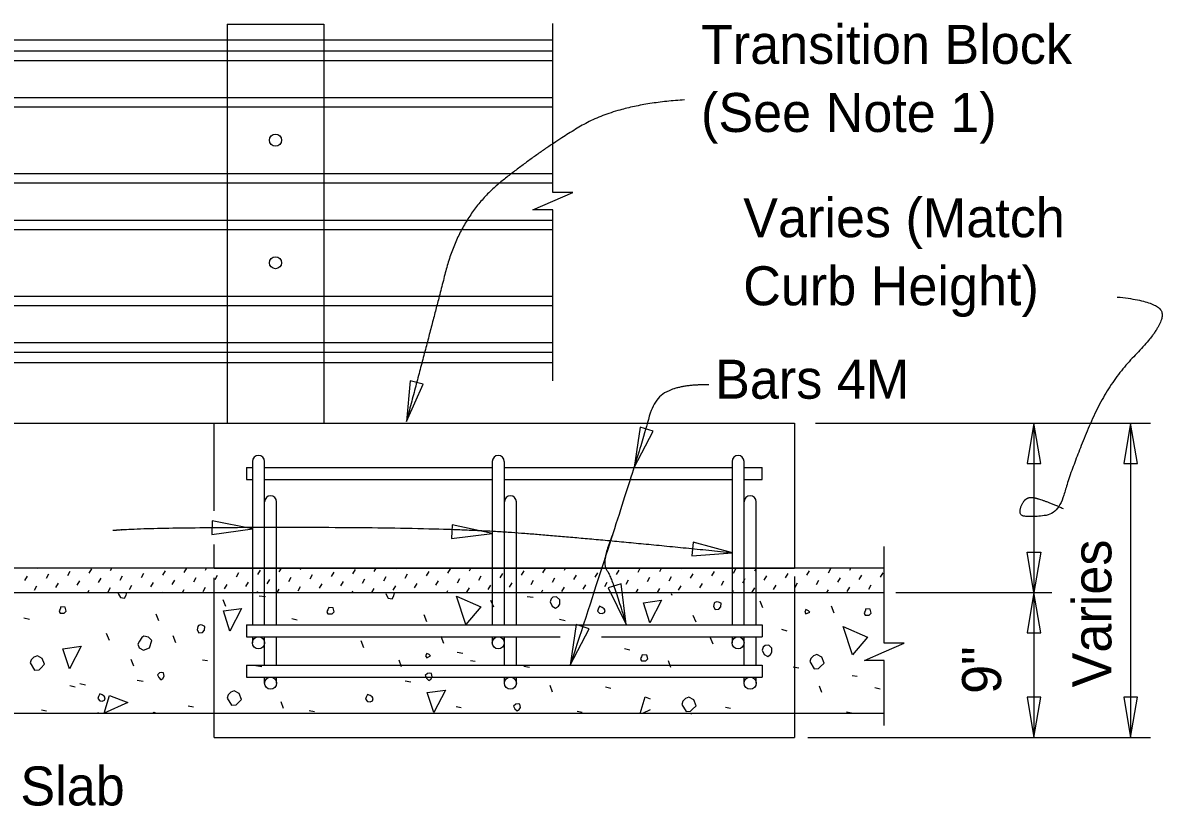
# Model space of a CAD drawing. Extents: x 21526.6 to 21598.7, y 56118.9 to 56155.9.
# Drawn here: x 21561.42 to 21567.31, y 56133.17 to 56137.28 of the extents above; entities that cross this region are included whole.
import ezdxf

# ---------------------------------------------------------------- set-up
doc = ezdxf.new("R2010")
doc.units = 0
for name, color, linetype in [('AdhocPoint_dp', 7, 'Continuous'), ('Border', 7, 'Continuous'), ('Patterning', 7, 'Continuous'), ('PlotBorder_dp', 7, 'Continuous'), ('SheetBorder_dp', 7, 'Continuous'), ('SheetLines_dp', 7, 'Continuous'), ('SubStrConc', 7, 'Continuous'), ('SubStrConc_h', 7, 'Continuous')]:
    doc.layers.add(name, color=color, linetype=linetype)

msp = doc.modelspace()

# ---------------------------------------------------------------- linework, layer by layer
at = {"layer": 'AdhocPoint_dp'}
for p, q in [((21554.3018, 56135.21), (21562.4118, 56135.21)), ((21565.8764, 56134.4601), (21554.3018, 56134.4601)), ((21554.3018, 56134.3351), (21565.8764, 56134.3351)), ((21565.8764, 56133.71), (21559.5217, 56133.71))]:
    msp.add_line(p, q, dxfattribs=at)
at = {"layer": 'Patterning'}
for p, q in [((21562.4788, 56137.2725), (21562.4788, 56135.21)), ((21562.4788, 56137.2725), (21562.9788, 56137.2725)), ((21562.9788, 56137.2725), (21562.9788, 56135.21)), ((21561.4336, 56134.3964), (21561.4465, 56134.4187)), ((21561.4954, 56134.4582), (21561.4965, 56134.4601)), ((21561.5442, 56134.4093), (21561.5572, 56134.4317)), ((21561.6548, 56134.4223), (21561.6678, 56134.4447)), ((21561.7655, 56134.4352), (21561.7784, 56134.4576)), ((21561.8761, 56134.4482), (21561.883, 56134.4601)), ((21561.9249, 56134.3994), (21561.9379, 56134.4218)), ((21562.0356, 56134.4123), (21562.0485, 56134.4347)), ((21562.1462, 56134.4253), (21562.1592, 56134.4477)), ((21562.2568, 56134.4383), (21562.2695, 56134.4601)), ((21562.3675, 56134.4512), (21562.3726, 56134.4601)), ((21562.4163, 56134.4024), (21562.4293, 56134.4248)), ((21562.5269, 56134.4154), (21562.5399, 56134.4377)), ((21562.6376, 56134.4283), (21562.6505, 56134.4507)), ((21562.7482, 56134.4413), (21562.7591, 56134.4601)), ((21562.797, 56134.3925), (21562.81, 56134.4148)), ((21562.8588, 56134.4542), (21562.8622, 56134.4601)), ((21562.9077, 56134.4054), (21562.9206, 56134.4278)), ((21563.0183, 56134.4184), (21563.0312, 56134.4408)), ((21563.1289, 56134.4313), (21563.1419, 56134.4537)), ((21563.2396, 56134.4443), (21563.2487, 56134.4601)), ((21563.2884, 56134.3955), (21563.3013, 56134.4179)), ((21563.3502, 56134.4573), (21563.3518, 56134.4601)), ((21563.399, 56134.4084), (21563.412, 56134.4308)), ((21563.5097, 56134.4214), (21563.5226, 56134.4438)), ((21563.6203, 56134.4344), (21563.6332, 56134.4568)), ((21563.7309, 56134.4473), (21563.7383, 56134.4601)), ((21563.7798, 56134.3985), (21563.7927, 56134.4209)), ((21563.8904, 56134.4115), (21563.9033, 56134.4338)), ((21564.001, 56134.4244), (21564.014, 56134.4468)), ((21564.1116, 56134.4374), (21564.1246, 56134.4598)), ((21564.2223, 56134.4503), (21564.2279, 56134.4601)), ((21564.2711, 56134.4015), (21564.2841, 56134.4239)), ((21564.3817, 56134.4145), (21564.3947, 56134.4369)), ((21564.4924, 56134.4274), (21564.5053, 56134.4498)), ((21564.603, 56134.4404), (21564.6144, 56134.4601)), ((21564.6518, 56134.3916), (21564.6648, 56134.414)), ((21564.7151, 56134.4443), (21564.7243, 56134.4601)), ((21564.764, 56134.3955), (21564.7769, 56134.4179)), ((21564.8258, 56134.4573), (21564.8274, 56134.4601)), ((21564.8746, 56134.4084), (21564.8876, 56134.4308)), ((21564.9852, 56134.4214), (21564.9982, 56134.4438)), ((21565.0959, 56134.4344), (21565.1088, 56134.4568)), ((21565.2065, 56134.4473), (21565.2139, 56134.4601)), ((21565.2553, 56134.3985), (21565.2683, 56134.4209)), ((21565.366, 56134.4115), (21565.3789, 56134.4338)), ((21565.4766, 56134.4244), (21565.4896, 56134.4468)), ((21565.5872, 56134.4374), (21565.6002, 56134.4598)), ((21565.6979, 56134.4503), (21565.7035, 56134.4601)), ((21565.7467, 56134.4015), (21565.7597, 56134.4239)), ((21565.8573, 56134.4145), (21565.8703, 56134.4369)), ((21561.4824, 56134.3475), (21561.4954, 56134.3699)), ((21561.593, 56134.3605), (21561.606, 56134.3829)), ((21561.7037, 56134.3734), (21561.7166, 56134.3958)), ((21561.8143, 56134.3864), (21561.8273, 56134.4088)), ((21561.8631, 56134.3376), (21561.8761, 56134.36)), ((21561.9738, 56134.3505), (21561.9867, 56134.3729)), ((21562.0844, 56134.3635), (21562.0974, 56134.3859)), ((21562.195, 56134.3765), (21562.208, 56134.3989)), ((21562.3057, 56134.3894), (21562.3186, 56134.4118)), ((21562.3545, 56134.3406), (21562.3675, 56134.363)), ((21562.4651, 56134.3536), (21562.4781, 56134.376)), ((21562.5758, 56134.3665), (21562.5887, 56134.3889)), ((21562.6864, 56134.3795), (21562.6994, 56134.4019)), ((21562.8459, 56134.3436), (21562.8588, 56134.366)), ((21562.9565, 56134.3566), (21562.9695, 56134.379)), ((21563.0671, 56134.3695), (21563.0801, 56134.3919)), ((21563.1778, 56134.3825), (21563.1907, 56134.4049)), ((21563.2274, 56134.3351), (21563.2396, 56134.3561)), ((21563.3372, 56134.3466), (21563.3502, 56134.369)), ((21563.4479, 56134.3596), (21563.4608, 56134.382)), ((21563.5585, 56134.3726), (21563.5714, 56134.395)), ((21563.6691, 56134.3855), (21563.6821, 56134.4079)), ((21563.718, 56134.3367), (21563.7309, 56134.3591)), ((21563.8286, 56134.3497), (21563.8415, 56134.372)), ((21563.9392, 56134.3626), (21563.9522, 56134.385)), ((21564.0499, 56134.3756), (21564.0628, 56134.398)), ((21564.1605, 56134.3885), (21564.1734, 56134.4109)), ((21564.2093, 56134.3397), (21564.2223, 56134.3621)), ((21564.32, 56134.3527), (21564.3329, 56134.3751)), ((21564.4306, 56134.3656), (21564.4435, 56134.388)), ((21564.5412, 56134.3786), (21564.5542, 56134.401)), ((21564.703, 56134.3351), (21564.7151, 56134.3561)), ((21564.8128, 56134.3466), (21564.8258, 56134.369)), ((21564.9234, 56134.3596), (21564.9364, 56134.382)), ((21565.0341, 56134.3726), (21565.047, 56134.395)), ((21565.1447, 56134.3855), (21565.1577, 56134.4079)), ((21565.1935, 56134.3367), (21565.2065, 56134.3591)), ((21565.3042, 56134.3497), (21565.3171, 56134.372)), ((21565.4148, 56134.3626), (21565.4278, 56134.385)), ((21565.5254, 56134.3756), (21565.5384, 56134.398)), ((21565.6361, 56134.3885), (21565.649, 56134.4109)), ((21565.6849, 56134.3397), (21565.6979, 56134.3621)), ((21565.7955, 56134.3527), (21565.8085, 56134.3751)), ((21561.7585, 56134.3351), (21561.7655, 56134.347)), ((21562.145, 56134.3351), (21562.1462, 56134.3371)), ((21562.2482, 56134.3351), (21562.2568, 56134.35)), ((21562.4721, 56134.2625), (21562.458, 56134.2979)), ((21562.6346, 56134.3351), (21562.6376, 56134.3401)), ((21562.6448, 56134.3185), (21562.6766, 56134.315)), ((21562.7378, 56134.3351), (21562.7482, 56134.353)), ((21563.1243, 56134.3351), (21563.1289, 56134.3431)), ((21563.6139, 56134.3351), (21563.6203, 56134.3461)), ((21564.0004, 56134.3351), (21564.001, 56134.3362)), ((21564.0294, 56134.315), (21564.0613, 56134.3114)), ((21564.1035, 56134.3351), (21564.1116, 56134.3491)), ((21564.49, 56134.3351), (21564.4924, 56134.3392)), ((21564.5931, 56134.3351), (21564.603, 56134.3522)), ((21565.0895, 56134.3351), (21565.0959, 56134.3461)), ((21565.476, 56134.3351), (21565.4766, 56134.3362)), ((21565.5791, 56134.3351), (21565.5872, 56134.3491)), ((21563.8568, 56134.259), (21563.8427, 56134.2944)), ((21565.2489, 56134.2557), (21565.2347, 56134.291)), ((21565.6176, 56134.2282), (21565.6035, 56134.2636)), ((21561.428, 56134.2036), (21561.4563, 56134.1965)), ((21562.1263, 56134.1877), (21562.1121, 56134.223)), ((21562.8127, 56134.2001), (21562.841, 56134.193)), ((21563.511, 56134.1841), (21563.4968, 56134.2195)), ((21564.1974, 56134.1965), (21564.2257, 56134.1894)), ((21564.903, 56134.1808), (21564.8889, 56134.2161)), ((21561.87, 56134.0869), (21561.8558, 56134.1223)), ((21565.3441, 56134.1447), (21565.3724, 56134.1376)), ((21562.214, 56134.0752), (21562.1999, 56134.1105)), ((21563.1862, 56134.0491), (21563.172, 56134.0845)), ((21563.5987, 56134.0716), (21563.5846, 56134.107)), ((21564.9908, 56134.0683), (21564.9767, 56134.1036)), ((21563.6672, 56134.0268), (21563.6973, 56134.0215)), ((21564.5329, 56134.0454), (21564.5612, 56134.0384)), ((21561.9955, 56133.9543), (21561.9831, 56133.9879)), ((21562.3519, 56133.9868), (21562.3767, 56133.9832)), ((21562.6277, 56133.9585), (21562.6578, 56133.9532)), ((21563.3802, 56133.9508), (21563.3678, 56133.9844)), ((21563.7366, 56133.9832), (21563.7614, 56133.9797)), ((21564.0124, 56133.955), (21564.0424, 56133.9497)), ((21564.7722, 56133.9474), (21564.7598, 56133.981)), ((21565.4045, 56133.9516), (21565.4345, 56133.9463)), ((21565.7105, 56133.9057), (21565.7353, 56133.9022)), ((21561.6655, 56133.8542), (21561.6938, 56133.8471)), ((21561.7179, 56133.8642), (21561.7462, 56133.8571)), ((21562.0143, 56133.8825), (21562.0443, 56133.8772)), ((21563.399, 56133.8789), (21563.429, 56133.8736)), ((21564.1609, 56133.8206), (21564.1485, 56133.8542)), ((21564.4349, 56133.8471), (21564.4632, 56133.8401)), ((21565.5529, 56133.8173), (21565.5406, 56133.8508)), ((21565.8269, 56133.8438), (21565.8552, 56133.8367)), ((21562.7705, 56133.7357), (21562.7581, 56133.7693)), ((21561.5188, 56133.7287), (21561.5453, 56133.7234)), ((21561.8135, 56133.71), (21561.8116, 56133.7152)), ((21562.2777, 56133.7499), (21562.3042, 56133.7446)), ((21562.9035, 56133.7251), (21562.93, 56133.7198)), ((21563.1969, 56133.71), (21563.1963, 56133.7116)), ((21563.6624, 56133.7464), (21563.6889, 56133.7411)), ((21564.2882, 56133.7216), (21564.3147, 56133.7163)), ((21565.0544, 56133.743), (21565.0809, 56133.7377)), ((21565.6802, 56133.7183), (21565.7067, 56133.713))]:
    msp.add_line(p, q, dxfattribs=at)
for points in [[(21561.915, 56134.3351), (21561.9142, 56134.3326), (21561.9177, 56134.3256)], [(21561.9177, 56134.3256), (21561.9265, 56134.3097), (21561.9477, 56134.3061), (21561.9566, 56134.322), (21561.9598, 56134.3351)], [(21563.3008, 56134.3351), (21563.2988, 56134.3291), (21563.3024, 56134.322)], [(21563.3024, 56134.322), (21563.3112, 56134.3061), (21563.3324, 56134.3026), (21563.3413, 56134.3185), (21563.3448, 56134.3326), (21563.3424, 56134.3351)], [(21563.7121, 56134.1696), (21563.6644, 56134.3163), (21563.7899, 56134.2615), (21563.7121, 56134.1696)], [(21564.1486, 56134.2859), (21564.1592, 56134.2647), (21564.1769, 56134.2541), (21564.191, 56134.2647), (21564.1981, 56134.2753), (21564.1981, 56134.2965), (21564.1822, 56134.3124), (21564.1627, 56134.3106), (21564.1539, 56134.3018), (21564.1486, 56134.2859)], [(21564.7764, 56134.3351), (21564.7744, 56134.3291), (21564.7779, 56134.322)], [(21561.6154, 56134.2283), (21561.6366, 56134.2283), (21561.6472, 56134.2389), (21561.6419, 56134.2584), (21561.6189, 56134.2602), (21561.6154, 56134.2495), (21561.6101, 56134.2407), (21561.6154, 56134.2283), (21561.6119, 56134.2319)], [(21562.4929, 56134.1357), (21562.4593, 56134.24), (21562.553, 56134.2524), (21562.4929, 56134.1357)], [(21563.0001, 56134.2248), (21563.0213, 56134.2248), (21563.0319, 56134.2354), (21563.0266, 56134.2549), (21563.0036, 56134.2566), (21563.0001, 56134.246), (21562.9948, 56134.2372), (21563.0001, 56134.2248), (21562.9965, 56134.2283)], [(21564.4044, 56134.2281), (21564.4168, 56134.2263), (21564.4292, 56134.2316), (21564.4327, 56134.2423), (21564.4274, 56134.2511), (21564.4168, 56134.2582), (21564.4044, 56134.2635), (21564.3973, 56134.2493), (21564.3938, 56134.2387), (21564.4044, 56134.2281)], [(21564.6643, 56134.1779), (21564.6307, 56134.2822), (21564.7244, 56134.2945), (21564.6643, 56134.1779)], [(21564.9933, 56134.2627), (21565.0022, 56134.2468), (21565.0216, 56134.2485), (21565.0304, 56134.2609), (21565.0322, 56134.2803), (21565.0198, 56134.2856), (21565.011, 56134.2874), (21565.0004, 56134.2839), (21564.9968, 56134.2803), (21564.9933, 56134.2627)], [(21565.4713, 56134.2251), (21565.4908, 56134.2339), (21565.4837, 56134.241), (21565.4713, 56134.2463), (21565.466, 56134.2339), (21565.4713, 56134.2251)], [(21565.7768, 56134.2179), (21565.798, 56134.2179), (21565.8086, 56134.2285), (21565.8033, 56134.248), (21565.7804, 56134.2497), (21565.7768, 56134.2391), (21565.7715, 56134.2303), (21565.7768, 56134.2179), (21565.7733, 56134.2215)], [(21562.3237, 56134.1423), (21562.3325, 56134.1264), (21562.3519, 56134.1282), (21562.3608, 56134.1406), (21562.3625, 56134.16), (21562.3502, 56134.1653), (21562.3413, 56134.1671), (21562.3307, 56134.1636), (21562.3272, 56134.16), (21562.3237, 56134.1423)], [(21565.7117, 56134.0122), (21565.664, 56134.1589), (21565.7895, 56134.1041), (21565.7117, 56134.0122)], [(21562.0238, 56134.0498), (21562.0467, 56134.0374), (21562.0768, 56134.0498), (21562.0892, 56134.0869), (21562.0715, 56134.1046), (21562.0485, 56134.1099), (21562.0379, 56134.1028), (21562.0255, 56134.0834), (21562.0167, 56134.0675), (21562.0238, 56134.0498)], [(21565.2454, 56134.0365), (21565.256, 56134.0152), (21565.2736, 56134.0046), (21565.2878, 56134.0152), (21565.2948, 56134.0259), (21565.2948, 56134.0471), (21565.2789, 56134.063), (21565.2595, 56134.0612), (21565.2507, 56134.0524), (21565.2454, 56134.0365)], [(21561.4605, 56133.9709), (21561.4834, 56133.9337), (21561.5064, 56133.9355), (21561.5153, 56133.9444), (21561.5347, 56133.9638), (21561.5223, 56133.9938), (21561.4976, 56134.008), (21561.4799, 56134.0009), (21561.4658, 56133.9868), (21561.4605, 56133.9709)], [(21561.6631, 56133.9402), (21561.6295, 56134.0445), (21561.7232, 56134.0569), (21561.6631, 56133.9402)], [(21563.5103, 56133.998), (21563.5298, 56134.0068), (21563.5227, 56134.0139), (21563.5103, 56134.0192), (21563.505, 56134.0068), (21563.5103, 56133.998)], [(21564.6215, 56133.9816), (21564.6427, 56133.9816), (21564.6533, 56133.9922), (21564.648, 56134.0116), (21564.625, 56134.0134), (21564.6215, 56134.0028), (21564.6162, 56133.994), (21564.6215, 56133.9816), (21564.618, 56133.9851)], [(21565.4907, 56133.9776), (21565.5137, 56133.9404), (21565.5366, 56133.9422), (21565.5455, 56133.9511), (21565.5649, 56133.9705), (21565.5526, 56134.0005), (21565.5278, 56134.0147), (21565.5101, 56134.0076), (21565.496, 56133.9935), (21565.4907, 56133.9776)], [(21562.1257, 56133.8949), (21562.1363, 56133.8842), (21562.1469, 56133.8913), (21562.1539, 56133.9019), (21562.1504, 56133.9196), (21562.1416, 56133.9214), (21562.1292, 56133.9196), (21562.1186, 56133.909), (21562.1257, 56133.8949)], [(21563.5103, 56133.8913), (21563.5209, 56133.8807), (21563.5316, 56133.8878), (21563.5386, 56133.8984), (21563.5351, 56133.9161), (21563.5262, 56133.9178), (21563.5139, 56133.9161), (21563.5033, 56133.9055), (21563.5103, 56133.8913)], [(21562.4785, 56133.7897), (21562.5015, 56133.7526), (21562.5245, 56133.7544), (21562.5333, 56133.7632), (21562.5528, 56133.7827), (21562.5404, 56133.8127), (21562.5156, 56133.8269), (21562.498, 56133.8198), (21562.4838, 56133.8056), (21562.4785, 56133.7897)], [(21563.547, 56133.7141), (21563.5134, 56133.8184), (21563.6071, 56133.8308), (21563.547, 56133.7141)], [(21561.8205, 56133.7758), (21561.8328, 56133.774), (21561.8452, 56133.7793), (21561.8487, 56133.7899), (21561.8434, 56133.7988), (21561.8328, 56133.8058), (21561.8205, 56133.8111), (21561.8134, 56133.797), (21561.8099, 56133.7864), (21561.8205, 56133.7758)], [(21561.8428, 56133.711), (21561.8711, 56133.8029), (21561.9648, 56133.7658), (21561.8428, 56133.711)], [(21563.2051, 56133.7723), (21563.2175, 56133.7705), (21563.2299, 56133.7758), (21563.2334, 56133.7864), (21563.2281, 56133.7952), (21563.2175, 56133.8023), (21563.2051, 56133.8076), (21563.1981, 56133.7935), (21563.1945, 56133.7829), (21563.2051, 56133.7723)], [(21564.6141, 56133.71), (21564.6405, 56133.7959), (21564.6652, 56133.7861)], [(21564.8288, 56133.7569), (21564.8518, 56133.7198), (21564.8748, 56133.7216), (21564.8836, 56133.7304), (21564.9031, 56133.7499), (21564.8907, 56133.7799), (21564.8659, 56133.794), (21564.8483, 56133.787), (21564.8341, 56133.7728), (21564.8288, 56133.7569)], [(21562.1099, 56133.71), (21562.1009, 56133.7145), (21562.0934, 56133.71)], [(21563.4875, 56133.71), (21563.4856, 56133.711), (21563.484, 56133.71)], [(21563.9669, 56133.7339), (21563.9775, 56133.7233), (21563.9881, 56133.7304), (21563.9951, 56133.741), (21563.9916, 56133.7586), (21563.9828, 56133.7604), (21563.9704, 56133.7586), (21563.9598, 56133.748), (21563.9669, 56133.7339)], [(21564.6652, 56133.7277), (21564.6258, 56133.71)], [(21564.8796, 56133.7067), (21564.8777, 56133.7077), (21564.876, 56133.7067)]]:
    msp.add_lwpolyline(points, dxfattribs=at)
at = {"layer": 'PlotBorder_dp'}
for p, q in [((21565.5209, 56135.21), (21567.2532, 56135.21)), ((21566.6495, 56135.21), (21566.6495, 56133.585)), ((21567.1495, 56135.21), (21567.1495, 56133.585)), ((21565.9364, 56134.335), (21566.742, 56134.335)), ((21565.4809, 56133.585), (21567.2532, 56133.585))]:
    msp.add_line(p, q, dxfattribs=at)
for points in [[(21564.1633, 56135.429), (21564.1633, 56136.3122), (21564.0599, 56136.3122), (21564.1633, 56136.3572), (21564.2666, 56136.4022), (21564.1633, 56136.4022), (21564.1633, 56137.2752)], [(21565.8764, 56133.6472), (21565.8764, 56133.9832), (21565.7731, 56133.9832), (21565.8764, 56134.0282), (21565.9797, 56134.0732), (21565.8764, 56134.0732), (21565.8764, 56134.5731)]]:
    msp.add_lwpolyline(points, dxfattribs=at)
for points in [[(21563.4053, 56135.2188), (21563.4928, 56135.4111), (21563.4245, 56135.4291)], [(21564.5839, 56134.9808), (21564.6819, 56135.1679), (21564.6148, 56135.1898)], [(21566.6495, 56135.21), (21566.6142, 56135.0017), (21566.6848, 56135.0017)], [(21567.1495, 56135.21), (21567.1142, 56135.0017), (21567.1848, 56135.0017)], [(21562.6093, 56134.6644), (21562.4019, 56134.7045), (21562.4003, 56134.634)], [(21563.8483, 56134.6403), (21563.6418, 56134.6846), (21563.6388, 56134.6141)], [(21565.0916, 56134.5393), (21564.8879, 56134.5955), (21564.8808, 56134.5253)], [(21566.6495, 56134.335), (21566.6142, 56134.5432), (21566.6848, 56134.5432)], [(21564.5411, 56134.1696), (21564.5162, 56134.3794), (21564.4485, 56134.3595)], [(21566.6495, 56134.335), (21566.6142, 56134.1267), (21566.6848, 56134.1267)], [(21564.2526, 56133.9599), (21564.3506, 56134.147), (21564.2835, 56134.1689)], [(21566.6495, 56133.585), (21566.6848, 56133.7933), (21566.6142, 56133.7933)], [(21567.1495, 56133.585), (21567.1848, 56133.7933), (21567.1142, 56133.7933)]]:
    msp.add_lwpolyline(points, close=True, dxfattribs=at)
for points in [[(21564.8436, 56136.8807), (21564.5025, 56136.8595), (21564.1187, 56136.6348), (21563.685, 56136.2922), (21563.5309, 56135.6927), (21563.4053, 56135.2188)], [(21567.0807, 56135.8621), (21567.3115, 56135.8395), (21567.3147, 56135.7056), (21567.0236, 56135.4087), (21566.8353, 56134.952), (21566.7782, 56134.7407), (21566.6298, 56134.7236), (21566.5671, 56134.735), (21566.6013, 56134.8264), (21566.6698, 56134.8264), (21566.8011, 56134.7693)], [(21564.9691, 56135.4078), (21564.8456, 56135.4112), (21564.6854, 56135.3477), (21564.6319, 56135.124), (21564.2525, 56133.9599)], [(21565.0915, 56134.5393), (21564.3611, 56134.6135), (21563.6022, 56134.6706), (21562.0343, 56134.6706), (21561.8872, 56134.6546)], [(21564.4705, 56134.6317), (21564.412, 56134.4912), (21564.4698, 56134.4123), (21564.5411, 56134.1696)]]:
    msp.add_open_spline(points, degree=2, dxfattribs=at)
at = {"layer": 'SheetBorder_dp'}
for p, q in [((21564.1633, 56137.1891), (21552.8484, 56137.1891)), ((21552.8484, 56137.1336), (21564.1633, 56137.1336)), ((21552.8484, 56137.0853), (21564.1633, 56137.0853)), ((21552.8484, 56136.8925), (21564.1633, 56136.8925)), ((21552.8484, 56136.8443), (21564.1633, 56136.8443)), ((21552.8484, 56136.5003), (21564.1633, 56136.5003)), ((21552.8484, 56136.4521), (21564.1633, 56136.4521)), ((21552.8484, 56136.2593), (21564.1633, 56136.2593)), ((21552.8484, 56136.2112), (21564.1633, 56136.2112)), ((21552.8484, 56135.8672), (21564.1633, 56135.8672)), ((21552.8484, 56135.819), (21564.1633, 56135.819)), ((21552.8484, 56135.6262), (21564.1633, 56135.6262)), ((21552.8484, 56135.5779), (21564.1633, 56135.5779)), ((21564.1633, 56135.5224), (21552.8484, 56135.5224))]:
    msp.add_line(p, q, dxfattribs=at)
for centre in [(21562.7288, 56136.6724), (21562.7288, 56136.0393)]:
    msp.add_circle(centre, 0.0312, dxfattribs=at)
at = {"layer": 'SheetLines_dp'}
for p, q in [((21562.6097, 56135.0121), (21562.6097, 56134.1683)), ((21562.6722, 56134.1683), (21562.6722, 56135.0121)), ((21563.8493, 56135.0121), (21563.8493, 56134.1683)), ((21563.9118, 56134.1683), (21563.9118, 56135.0121)), ((21565.0889, 56135.0121), (21565.0889, 56134.1683)), ((21565.1514, 56134.1683), (21565.1514, 56135.0121)), ((21562.5785, 56134.9808), (21562.6097, 56134.9808)), ((21562.5785, 56134.9808), (21562.5785, 56134.9183)), ((21562.6722, 56134.9808), (21563.8493, 56134.9808)), ((21563.9118, 56134.9808), (21565.0889, 56134.9808)), ((21565.1514, 56134.9808), (21565.2451, 56134.9808)), ((21565.2451, 56134.9183), (21565.2451, 56134.9808)), ((21562.5785, 56134.9183), (21562.6097, 56134.9183)), ((21562.6722, 56134.9183), (21563.8493, 56134.9183)), ((21563.9118, 56134.9183), (21565.0889, 56134.9183)), ((21565.1514, 56134.9183), (21565.2451, 56134.9183)), ((21562.7347, 56134.1683), (21562.7347, 56134.8038)), ((21563.9743, 56134.1683), (21563.9743, 56134.8038)), ((21565.2139, 56134.1683), (21565.2139, 56134.8038)), ((21562.5785, 56134.1683), (21562.5785, 56134.1058)), ((21562.5785, 56134.1683), (21565.2451, 56134.1683)), ((21565.2451, 56134.1683), (21565.2451, 56134.1058)), ((21562.5785, 56134.1058), (21564.1999, 56134.1058)), ((21562.6097, 56134.1058), (21562.6097, 56134.0745)), ((21562.6722, 56133.9599), (21562.6722, 56134.1058)), ((21562.7347, 56133.9599), (21562.7347, 56134.1058)), ((21563.8493, 56134.1058), (21563.8493, 56134.0745)), ((21563.9118, 56133.9599), (21563.9118, 56134.1058)), ((21563.9743, 56133.9599), (21563.9743, 56134.1058)), ((21564.4139, 56134.1058), (21565.2451, 56134.1058)), ((21565.0889, 56134.1058), (21565.0889, 56134.0745)), ((21565.1514, 56133.9599), (21565.1514, 56134.1058)), ((21565.2139, 56133.9599), (21565.2139, 56134.1058)), ((21562.5785, 56133.9599), (21562.5785, 56133.8975)), ((21562.5785, 56133.9599), (21565.2451, 56133.9599)), ((21565.2451, 56133.9599), (21565.2451, 56133.8975)), ((21562.5785, 56133.8975), (21565.2451, 56133.8975)), ((21562.6722, 56133.8662), (21562.6722, 56133.8975)), ((21562.7347, 56133.8662), (21562.7347, 56133.8975)), ((21563.9118, 56133.8662), (21563.9118, 56133.8975)), ((21563.9743, 56133.8662), (21563.9743, 56133.8975)), ((21565.1514, 56133.8662), (21565.1514, 56133.8975)), ((21565.2139, 56133.8662), (21565.2139, 56133.8975))]:
    msp.add_line(p, q, dxfattribs=at)
for centre in [(21562.6409, 56134.0745), (21563.8805, 56134.0745), (21565.1201, 56134.0745), (21562.7034, 56133.8662), (21563.943, 56133.8662), (21565.1826, 56133.8662)]:
    msp.add_circle(centre, 0.0312, dxfattribs=at)
for centre, radius, start, end in [((21562.6409, 56135.0121), 0.0312, 0, 180), ((21563.8805, 56135.0121), 0.0312, 0, 180), ((21565.1201, 56135.0121), 0.0312, 0, 180), ((21562.7034, 56134.8038), 0.0312, 0, 180), ((21563.943, 56134.8038), 0.0312, 0, 180), ((21565.1826, 56134.8038), 0.0312, 0, 180), ((21562.8709, 56133.1683), 1, 90, 90.00000277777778)]:
    msp.add_arc(centre, radius, start, end, dxfattribs=at)
at = {"layer": 'SubStrConc'}
for p, q in [((21562.4118, 56135.21), (21565.4118, 56135.21)), ((21562.4118, 56134.7572), (21562.4118, 56135.21)), ((21565.4118, 56135.21), (21565.4118, 56134.46)), ((21562.4118, 56134.46), (21562.4118, 56134.5835))]:
    msp.add_line(p, q, dxfattribs=at)
at = {"layer": 'SubStrConc_h'}
for p, q in [((21562.4118, 56134.46), (21565.4118, 56134.46)), ((21565.4118, 56134.417), (21565.4118, 56133.585)), ((21562.4118, 56133.585), (21562.4118, 56134.4115)), ((21562.4118, 56133.585), (21565.4118, 56133.585))]:
    msp.add_line(p, q, dxfattribs=at)

# ---------------------------------------------------------------- texts
at = {"layer": 'Border'}
for s, p in [('Bars 4M', (21565.0015, 56135.3365)), ('Existing Approach Slab', (21559.1619, 56133.2344))]:
    msp.add_text(s, height=0.2016, dxfattribs=at).set_placement(p)
for s, p in [('Varies', (21567.0502, 56133.8443)), ('9"', (21566.4798, 56133.8109))]:
    msp.add_text(s, height=0.2016, rotation=90, dxfattribs=at).set_placement(p)
at = {"layer": 'PlotBorder_dp'}
for s, p in [('Transition Block', (21564.9286, 56137.067)), ('(See Note 1)', (21564.9286, 56136.715)), ('Varies (Match', (21565.1469, 56136.1713)), ('Curb Height)', (21565.1469, 56135.8193))]:
    msp.add_text(s, height=0.2016, dxfattribs=at).set_placement(p)

doc.saveas('drawing.dxf')
